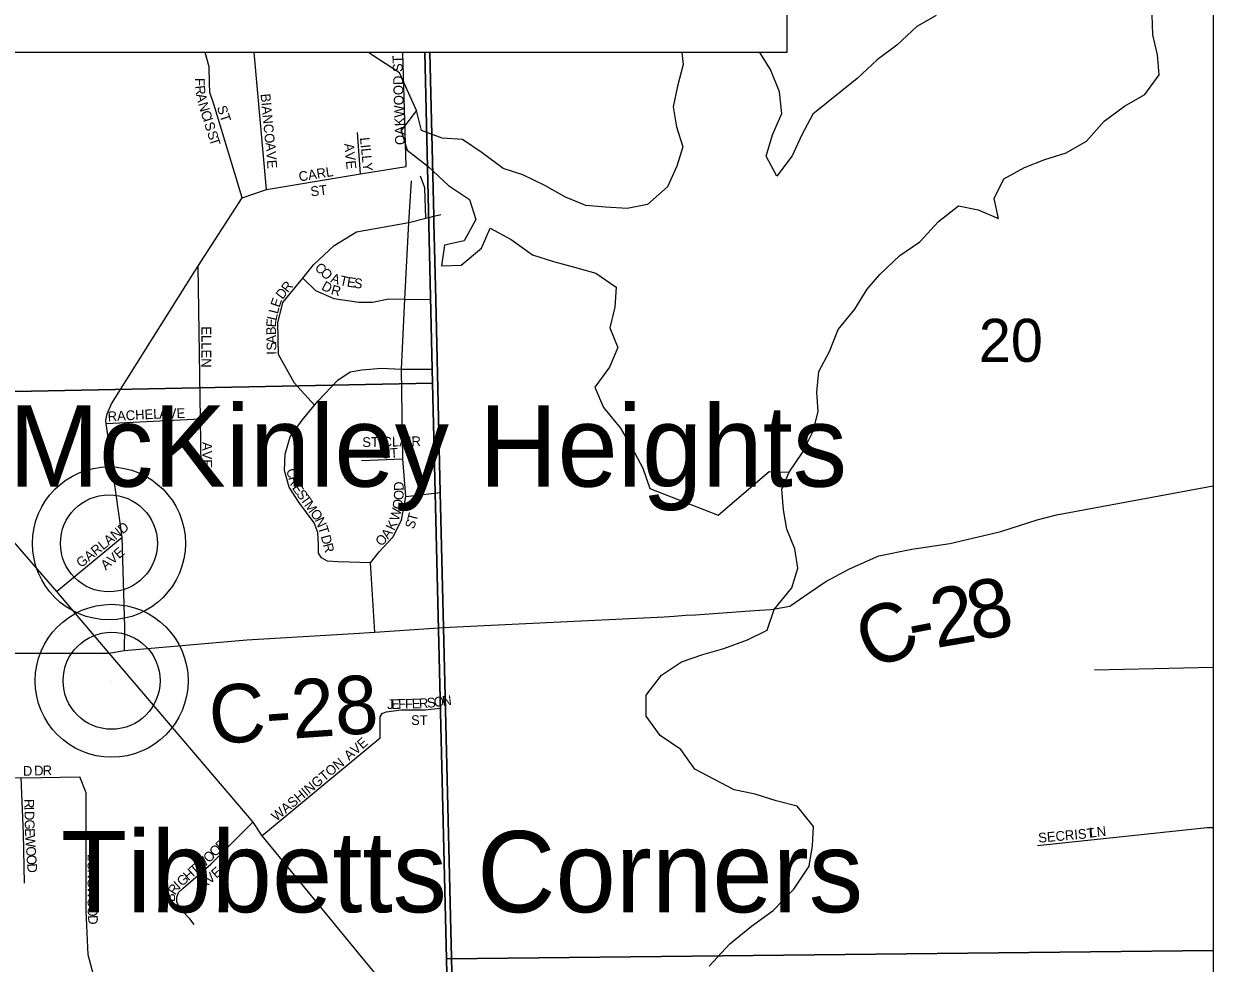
# Model space of a CAD drawing. Extents: x -37878.7 to -37844.7, y -19791.4 to -19769.4.
# Drawn here: x -37870.308 to -37869.15, y -19775.754 to -19774.84 of the extents above; entities that cross this region are included whole.
import ezdxf

# ---------------------------------------------------------------- set-up
doc = ezdxf.new("R2010")
doc.units = 0
for name, color, linetype in [('Default', 7, 'Continuous'), ('GM_X_City_Street', 7, 'Continuous'), ('GM_X_County_Road', 7, 'Continuous'), ('GM_X_County_Road_Text', 7, 'Continuous'), ('GM_X_Major_Lake', 7, 'Continuous'), ('GM_X_Minor_River', 7, 'Continuous'), ('GM_X_Section', 7, 'Continuous'), ('GM_X_Section_Text', 7, 'Continuous'), ('GM_X_State_Route', 7, 'Continuous'), ('GM_X_Township', 7, 'Continuous'), ('GM_X_Township_Subdivision', 7, 'Continuous'), ('GM_X_Township_Subdivision_Text', 7, 'Continuous'), ('GM_X_Unincorporated', 7, 'Continuous'), ('GM_X_Unincorporated_Text', 7, 'Continuous'), ('GM_X_US_Route', 7, 'Continuous'), ('SH_Data', 7, 'Continuous'), ('TX_P_1', 7, 'Continuous')]:
    doc.layers.add(name, color=color, linetype=linetype)

msp = doc.modelspace()

# ---------------------------------------------------------------- linework, layer by layer
at = {"layer": 'Default'}
for p, q in [((-37870.2249, -19775.3458), (-37870.2249, -19775.3458)), ((-37870.2223, -19775.4795), (-37870.2223, -19775.4795))]:
    msp.add_line(p, q, dxfattribs=at)
at = {"layer": 'GM_X_City_Street'}
for points in [[(-37869.5919, -19775.4109), (-37869.5804, -19775.4101), (-37869.5623, -19775.407), (-37869.5434, -19775.394), (-37869.5355, -19775.3885)], [(-37869.6542, -19775.4152), (-37869.6013, -19775.4115), (-37869.5919, -19775.4109)]]:
    msp.add_lwpolyline(points, dxfattribs=at)
at = {"layer": 'GM_X_County_Road'}
for points in [[(-37869.5355, -19775.3885), (-37869.5272, -19775.3829), (-37869.5043, -19775.3705), (-37869.4757, -19775.3579), (-37869.4436, -19775.3514), (-37869.4065, -19775.3459), (-37869.3805, -19775.3399), (-37869.3571, -19775.3344), (-37869.3216, -19775.3228), (-37869.3027, -19775.3181), (-37869.1504, -19775.2898)], [(-37869.6749, -19775.4166), (-37869.6638, -19775.4158), (-37869.6542, -19775.4152)], [(-37869.9866, -19775.4335), (-37869.9661, -19775.4323), (-37869.8993, -19775.4276), (-37869.8932, -19775.4273)], [(-37869.8932, -19775.4273), (-37869.6846, -19775.4173), (-37869.6749, -19775.4166)], [(-37870.2251, -19775.4526), (-37870.2099, -19775.45), (-37870.0908, -19775.4398), (-37869.9866, -19775.4335)]]:
    msp.add_lwpolyline(points, dxfattribs=at)
at = {"layer": 'GM_X_Major_Lake'}
msp.add_line((-37869.4852, -19775.0963), (-37869.4748, -19775.0842), dxfattribs=at)
for points in [[(-37869.4199, -19774.8323), (-37869.4389, -19774.8429), (-37869.4583, -19774.861), (-37869.4773, -19774.8753), (-37869.4967, -19774.8935), (-37869.5401, -19774.9282), (-37869.5508, -19774.9483), (-37869.56, -19774.9688), (-37869.5749, -19774.9884), (-37869.5854, -19774.969), (-37869.5792, -19774.9485), (-37869.57, -19774.9277), (-37869.5725, -19774.9064), (-37869.5811, -19774.8847), (-37869.5914, -19774.8684)], [(-37869.4748, -19775.0842), (-37869.4554, -19775.0657), (-37869.436, -19775.0525), (-37869.4177, -19775.0328), (-37869.3983, -19775.0173), (-37869.379, -19775.0212), (-37869.3594, -19775.0297), (-37869.3634, -19775.0103), (-37869.3542, -19774.9913), (-37869.3341, -19774.98), (-37869.3143, -19774.9725), (-37869.2935, -19774.9658), (-37869.2737, -19774.9545), (-37869.2566, -19774.9352), (-37869.2368, -19774.9205), (-37869.217, -19774.9092), (-37869.2029, -19774.8899), (-37869.2047, -19774.8705), (-37869.2091, -19774.8511), (-37869.2097, -19774.8317)], [(-37869.6675, -19774.8684), (-37869.6663, -19774.8798), (-37869.6717, -19774.901), (-37869.676, -19774.9211), (-37869.6727, -19774.9405), (-37869.6664, -19774.9599), (-37869.6722, -19774.9789), (-37869.6814, -19774.999), (-37869.7008, -19775.016), (-37869.7205, -19775.0201), (-37869.7417, -19775.0188), (-37869.761, -19775.0172), (-37869.7806, -19775.0091), (-37869.8006, -19774.9977), (-37869.8221, -19774.9873), (-37869.8414, -19774.9812), (-37869.8618, -19774.9659), (-37869.881, -19774.9529), (-37869.9007, -19774.9516), (-37869.9207, -19774.944), (-37869.9255, -19774.9246), (-37869.9404, -19774.9442), (-37869.9348, -19774.9633), (-37869.9145, -19774.9789), (-37869.8945, -19774.9976), (-37869.8742, -19775.0114), (-37869.8678, -19775.0308), (-37869.8793, -19775.0516), (-37869.8983, -19775.0557), (-37869.9014, -19775.0758), (-37869.8821, -19775.0751)], [(-37869.8821, -19775.0751), (-37869.8623, -19775.0585), (-37869.8539, -19775.0392), (-37869.8335, -19775.0503), (-37869.8128, -19775.0652), (-37869.7924, -19775.0717), (-37869.772, -19775.0772), (-37869.7512, -19775.0829), (-37869.7312, -19775.0967), (-37869.7328, -19775.1161), (-37869.7375, -19775.1362), (-37869.7296, -19775.1552), (-37869.7377, -19775.1745), (-37869.7522, -19775.1938), (-37869.7436, -19775.2136), (-37869.7271, -19775.2338), (-37869.7159, -19775.2532), (-37869.7054, -19775.2726), (-37869.6987, -19775.2924), (-37869.6322, -19775.3185), (-37869.5823, -19775.2758), (-37869.563, -19775.2767), (-37869.55, -19775.2574), (-37869.5397, -19775.2365), (-37869.5347, -19775.2176), (-37869.5361, -19775.1986), (-37869.534, -19775.1785), (-37869.5237, -19775.1592), (-37869.5152, -19775.1376), (-37869.4992, -19775.1179), (-37869.487, -19775.0986), (-37869.4852, -19775.0963)]]:
    msp.add_lwpolyline(points, dxfattribs=at)
at = {"layer": 'GM_X_Minor_River'}
for points in [[(-37869.9255, -19774.9246), (-37869.9421, -19774.8881), (-37869.9702, -19774.8697), (-37869.9719, -19774.8684)], [(-37869.6409, -19775.7571), (-37869.6207, -19775.7355), (-37869.5998, -19775.7182), (-37869.5785, -19775.7031), (-37869.5583, -19775.6823), (-37869.5434, -19775.6599), (-37869.5403, -19775.6402), (-37869.5394, -19775.6212), (-37869.5552, -19775.6014), (-37869.5756, -19775.5964), (-37869.596, -19775.5898), (-37869.6164, -19775.5856), (-37869.6549, -19775.5656), (-37869.6684, -19775.5462), (-37869.6884, -19775.5328), (-37869.7023, -19775.5138), (-37869.7022, -19775.4936), (-37869.6873, -19775.474), (-37869.6679, -19775.4611), (-37869.647, -19775.454), (-37869.6266, -19775.448), (-37869.6034, -19775.4398), (-37869.5844, -19775.4304), (-37869.5775, -19775.4103), (-37869.5603, -19775.3891), (-37869.5545, -19775.3701), (-37869.5574, -19775.3511), (-37869.5653, -19775.3321), (-37869.5686, -19775.3131), (-37869.57, -19775.293), (-37869.563, -19775.2767)]]:
    msp.add_lwpolyline(points, dxfattribs=at)
at = {"layer": 'GM_X_Section'}
for points in [[(-37869.9174, -19774.8684), (-37869.91, -19775.19), (-37871.0324, -19775.2124), (-37871.041, -19774.8684)], [(-37869.1504, -19775.742), (-37869.8966, -19775.75), (-37869.91, -19775.19), (-37869.9174, -19774.8684)], [(-37869.1504, -19776.7884), (-37869.8722, -19776.7987), (-37869.8839, -19776.3111), (-37869.8966, -19775.75), (-37869.1504, -19775.742)]]:
    msp.add_lwpolyline(points, dxfattribs=at)
msp.add_lwpolyline([(-37869.91, -19775.19), (-37869.8966, -19775.75), (-37869.8839, -19776.3111), (-37871.0074, -19776.3279), (-37871.0324, -19775.2124)], close=True, dxfattribs=at)
at = {"layer": 'GM_X_State_Route'}
msp.add_lwpolyline([(-37870.5559, -19775.4526), (-37870.5114, -19775.4526), (-37870.4536, -19775.4531), (-37870.4247, -19775.4526), (-37870.3932, -19775.4521), (-37870.3695, -19775.4526), (-37870.2251, -19775.4526)], dxfattribs=at)
at = {"layer": 'GM_X_Township'}
for points in [[(-37869.8525, -19777.3854), (-37869.8535, -19777.3423), (-37869.854, -19777.3235), (-37869.8592, -19777.1489), (-37869.8891, -19775.8564), (-37869.8993, -19775.4276), (-37869.9025, -19775.2964), (-37869.9069, -19775.1088), (-37869.9087, -19775.0336), (-37869.9089, -19775.0274), (-37869.9127, -19774.8684)], [(-37869.9127, -19774.8684), (-37869.9089, -19775.0274), (-37869.9087, -19775.0336), (-37869.9069, -19775.1088), (-37869.9025, -19775.2964), (-37869.8993, -19775.4276), (-37869.8891, -19775.8564), (-37869.8592, -19777.1489), (-37869.854, -19777.3235), (-37869.8535, -19777.3423), (-37869.8525, -19777.3854)]]:
    msp.add_lwpolyline(points, dxfattribs=at)
at = {"layer": 'GM_X_Township_Subdivision'}
for points in [[(-37870.0953, -19775.0095), (-37870.1023, -19774.9861), (-37870.1228, -19774.9186), (-37870.1268, -19774.9072), (-37870.1271, -19774.898), (-37870.1273, -19774.8821), (-37870.1313, -19774.8684)], [(-37870.0715, -19775.0014), (-37870.0836, -19774.8684)], [(-37869.9358, -19774.9792), (-37869.939, -19774.8684)], [(-37869.9802, -19774.9863), (-37869.9831, -19774.9461)], [(-37870.0953, -19775.0095), (-37870.0715, -19775.0014), (-37869.9802, -19774.9863), (-37869.9358, -19774.9792)], [(-37869.9661, -19775.4323), (-37869.9705, -19775.3648), (-37869.9621, -19775.354), (-37869.9487, -19775.3397), (-37869.9403, -19775.3232), (-37869.9361, -19775.3003), (-37869.9389, -19775.2637), (-37869.9403, -19775.1763), (-37869.9369, -19775.1082), (-37869.9331, -19775.0335), (-37869.9304, -19774.993)], [(-37869.9164, -19775.0293), (-37869.9176, -19775), (-37869.9217, -19774.9886)], [(-37870.2099, -19775.45), (-37870.2093, -19775.4274), (-37870.212, -19775.3397), (-37870.2277, -19775.2293), (-37870.2278, -19775.2263), (-37870.2267, -19775.2198), (-37870.2225, -19775.2102), (-37870.1414, -19775.081), (-37870.1385, -19775.0766), (-37870.0953, -19775.0095)], [(-37870.0249, -19775.2115), (-37870.0442, -19775.1898), (-37870.0598, -19775.1622), (-37870.0606, -19775.1314), (-37870.0558, -19775.1114), (-37870.0361, -19775.0877), (-37870.0258, -19775.0747), (-37870.0058, -19775.0559), (-37869.9839, -19775.0427), (-37869.9331, -19775.0335)], [(-37869.9331, -19775.0335), (-37869.9164, -19775.0293), (-37869.9124, -19775.0283)], [(-37869.9124, -19775.0283), (-37869.9089, -19775.0274), (-37869.9021, -19775.0257)], [(-37870.1385, -19775.0766), (-37870.1362, -19775.2247), (-37870.1355, -19775.2714)], [(-37870.0361, -19775.0877), (-37870.0238, -19775.0999), (-37870.0062, -19775.1075), (-37869.9819, -19775.111), (-37869.9683, -19775.111), (-37869.9527, -19775.1078), (-37869.9369, -19775.1082), (-37869.9119, -19775.1084)], [(-37869.9705, -19775.3648), (-37869.9911, -19775.3642), (-37870.0021, -19775.3638), (-37870.0121, -19775.3632), (-37870.0181, -19775.3598), (-37870.0209, -19775.3554), (-37870.0209, -19775.3472), (-37870.0215, -19775.3353), (-37870.0253, -19775.3259), (-37870.0403, -19775.3058), (-37870.0497, -19775.2911), (-37870.0541, -19775.2748), (-37870.0535, -19775.2591), (-37870.0485, -19775.2422), (-37870.0369, -19775.2259), (-37870.0249, -19775.2115), (-37870.0212, -19775.2071), (-37870.0021, -19775.187), (-37869.9902, -19775.1788), (-37869.9789, -19775.177), (-37869.9597, -19775.1754), (-37869.9403, -19775.1763), (-37869.911, -19775.1763)], [(-37870.2277, -19775.2293), (-37870.1362, -19775.2247)], [(-37869.979, -19775.2653), (-37869.9389, -19775.2637)], [(-37869.9361, -19775.3003), (-37869.9025, -19775.2964)], [(-37870.276, -19775.3927), (-37870.212, -19775.3397)], [(-37869.1504, -19775.4666), (-37869.2659, -19775.4693)], [(-37869.9551, -19775.5097), (-37869.9402, -19775.5077), (-37869.9171, -19775.5078), (-37869.9027, -19775.5061)], [(-37870.0761, -19775.6302), (-37869.961, -19775.535), (-37869.9609, -19775.5146), (-37869.9589, -19775.5112), (-37869.9551, -19775.5097)], [(-37870.3695, -19775.5729), (-37870.3102, -19775.5739), (-37870.2532, -19775.573)], [(-37870.307, -19775.6765), (-37870.3081, -19775.628), (-37870.3102, -19775.5739)], [(-37870.2258, -19775.806), (-37870.2388, -19775.7704), (-37870.2451, -19775.7462), (-37870.2472, -19775.7032), (-37870.2472, -19775.6527), (-37870.2472, -19775.5886), (-37870.2532, -19775.573)], [(-37870.142, -19775.7165), (-37870.1463, -19775.7111), (-37870.1534, -19775.7038), (-37870.1573, -19775.698), (-37870.1589, -19775.6946), (-37870.1588, -19775.6901), (-37870.1573, -19775.6856), (-37870.1528, -19775.6812), (-37870.1259, -19775.658), (-37870.085, -19775.6171)], [(-37869.3213, -19775.6396), (-37869.1561, -19775.6222), (-37869.1504, -19775.6221)]]:
    msp.add_lwpolyline(points, dxfattribs=at)
at = {"layer": 'GM_X_Unincorporated'}
for centre, radius in [((-37870.2249, -19775.3458), 0.0744), ((-37870.2249, -19775.3458), 0.0472), ((-37870.2223, -19775.4795), 0.0744), ((-37870.2223, -19775.4795), 0.0472)]:
    msp.add_circle(centre, radius, dxfattribs=at)
at = {"layer": 'GM_X_US_Route'}
for points in [[(-37870.4728, -19775.163), (-37870.455, -19775.1876), (-37870.3956, -19775.2549), (-37870.276, -19775.3927), (-37870.2251, -19775.4526)], [(-37870.2251, -19775.4526), (-37870.085, -19775.6171), (-37870.0761, -19775.6302), (-37870.0384, -19775.6761)], [(-37870.0384, -19775.6761), (-37869.9733, -19775.7555), (-37869.8891, -19775.8564), (-37869.8384, -19775.9237), (-37869.7923, -19775.98), (-37869.7601, -19776.0241), (-37869.745, -19776.0523), (-37869.7421, -19776.0678), (-37869.7288, -19776.105), (-37869.708, -19776.1606), (-37869.6824, -19776.2284), (-37869.6651, -19776.2779), (-37869.6516, -19776.3363), (-37869.6381, -19776.4743), (-37869.6331, -19776.5413), (-37869.6291, -19776.5618), (-37869.6234, -19776.5817), (-37869.5984, -19776.6319), (-37869.5916, -19776.6444)]]:
    msp.add_lwpolyline(points, dxfattribs=at)
at = {"layer": 'SH_Data'}
msp.add_line((-37869.1504, -19770.3854), (-37869.1504, -19777.3854), dxfattribs=at)
at = {"layer": 'TX_P_1'}
for p, q in [((-37869.5652, -19774.2693), (-37869.5652, -19774.8684)), ((-37869.5652, -19774.8684), (-37871.544, -19774.8684))]:
    msp.add_line(p, q, dxfattribs=at)

# ---------------------------------------------------------------- texts
at = {"layer": 'GM_X_County_Road_Text'}
for s, height, rotation, p in [('8', 0.0568, 12.2769, (-37869.383, -19775.4412)), ('2', 0.0568, 9.7335, (-37869.4202, -19775.4477)), ('C', 0.0568, 24.6883, (-37869.4817, -19775.4704)), ('-', 0.0568, 11.0038, (-37869.4427, -19775.4521)), ('C-28', 0.05682, 4.0142, (-37870.1257, -19775.5414))]:
    msp.add_text(s, height=height, rotation=rotation, dxfattribs=at).set_placement(p)
at = {"layer": 'GM_X_Section_Text'}
msp.add_text('20', height=0.04186, rotation=0, dxfattribs=at).set_placement((-37869.3784, -19775.1692))
at = {"layer": 'GM_X_Township_Subdivision_Text'}
for s, rotation, p in [('OAKWOOD ST', 91.8466, (-37869.9368, -19774.9581)), ('F', 270.3825, (-37870.1412, -19774.893)), ('R', 276.1676, (-37870.1411, -19774.9008)), ('A', 281.9071, (-37870.1401, -19774.9092)), ('N', 286.2625, (-37870.1382, -19774.9181)), ('BIANCO', 275.3905, (-37870.0774, -19774.9087)), ('C', 287.6379, (-37870.1358, -19774.9264)), ('ST', 288.4262, (-37870.12, -19774.9216)), ('I', 287.6524, (-37870.1335, -19774.9335)), ('S', 287.6271, (-37870.1323, -19774.9375)), ('S', 287.6531, (-37870.1295, -19774.9462)), ('T', 287.6276, (-37870.1275, -19774.9526)), ('LILLY', 275.7076, (-37869.9807, -19774.9512)), ('AVE', 274.0831, (-37870.0724, -19774.9562)), ('AVE', 275.9027, (-37869.9961, -19774.957)), ('CARL', 9.2121, (-37870.0395, -19774.9938)), ('ST', 7.1217, (-37870.0282, -19775.0083)), ('C', 317.5254, (-37870.0254, -19775.0787)), ('O', 317.5499, (-37870.0199, -19775.0837)), ('R', 50.7029, (-37870.0509, -19775.1025)), ('D', 332.213, (-37870.0189, -19775.0985)), ('A', 342.5759, (-37870.0098, -19775.0916)), ('T', 347.5061, (-37870.001, -19775.0943)), ('E', 351.7378, (-37869.9938, -19775.0959)), ('S', 351.5665, (-37869.9872, -19775.0969)), ('D', 52.2755, (-37870.056, -19775.1091)), ('R', 344.9218, (-37870.0095, -19775.1032)), ('E', 71.3663, (-37870.059, -19775.1168)), ('L', 77.6105, (-37870.062, -19775.1295)), ('L', 75.3906, (-37870.0606, -19775.1231)), ('ELLEN', 270, (-37870.1349, -19775.1347)), ('B', 91.4087, (-37870.0623, -19775.1431)), ('E', 85.8161, (-37870.0625, -19775.1358)), ('A', 91.4209, (-37870.0621, -19775.1514)), ('S', 91.4443, (-37870.0619, -19775.1581)), ('I', 91.3988, (-37870.0618, -19775.1622)), ('RACHEL', 3.0668, (-37870.2259, -19775.2271)), ('AVE', 1.9774, (-37870.1759, -19775.2246)), ('ST CLAIR', 0.9387, (-37869.9783, -19775.2521)), ('AVE', 270, (-37870.1341, -19775.2472)), ('CT', 3.1785, (-37869.9602, -19775.2633)), ('C', 284.4309, (-37870.0525, -19775.2743)), ('R', 286.6799, (-37870.0505, -19775.2819)), ('E', 303.3648, (-37870.0471, -19775.2918)), ('D', 93.0659, (-37869.9379, -19775.2945)), ('S', 305.748, (-37870.0431, -19775.2978)), ('T', 305.714, (-37870.0392, -19775.3032)), ('O', 86.739, (-37869.9384, -19775.3039)), ('M', 305.7254, (-37870.0354, -19775.3086)), ('W', 74.3872, (-37869.9431, -19775.3247)), ('O', 80.0124, (-37869.94, -19775.3133)), ('O', 305.7092, (-37870.0295, -19775.3167)), ('N', 294.5462, (-37870.0249, -19775.323)), ('K', 64.1782, (-37869.9474, -19775.334)), ('S', 67.8992, (-37869.9286, -19775.3327)), ('T', 75.3212, (-37869.9257, -19775.3252)), ('GARLAND', 39.0532, (-37870.252, -19775.37)), ('T', 287.2253, (-37870.0216, -19775.3303)), ('A', 53.6443, (-37869.9533, -19775.3423)), ('D', 285.1468, (-37870.0189, -19775.339)), ('R', 284.9111, (-37870.0168, -19775.347)), ('O', 47.6278, (-37869.9597, -19775.3493)), ('AVE', 40.8146, (-37870.228, -19775.3723)), ('E', 1.3386, (-37869.9501, -19775.507)), ('F', 1.351, (-37869.9434, -19775.5068)), ('F', 1.3522, (-37869.9367, -19775.5067)), ('E', 1.3386, (-37869.9301, -19775.5065)), ('R', 3.2827, (-37869.923, -19775.5063)), ('S', 6.6909, (-37869.9149, -19775.5059)), ('O', 7.126, (-37869.9082, -19775.5051)), ('N', 7.1196, (-37869.9, -19775.504)), ('J', 1.3556, (-37869.9542, -19775.5071)), ('ST', 0, (-37869.9309, -19775.5225)), ('AVE', 40.8174, (-37869.9912, -19775.5575)), ('WASHINGTON', 39.8044, (-37870.062, -19775.6167)), ('D', 1.2545, (-37870.3085, -19775.572)), ('D', 1.6834, (-37870.2976, -19775.5717)), ('R', 1.6761, (-37870.2893, -19775.5715)), ('R', 271.4573, (-37870.3074, -19775.5946)), ('I', 271.4425, (-37870.3072, -19775.6021)), ('D', 271.4428, (-37870.3071, -19775.6063)), ('G', 271.4633, (-37870.3069, -19775.6146)), ('E', 272.2588, (-37870.3067, -19775.6231)), ('SECRIST', 5.1935, (-37869.3202, -19775.6371)), ('LN', 6.0111, (-37869.2702, -19775.6321)), ('W', 273.5657, (-37870.3064, -19775.63)), ('D', 44.9992, (-37870.1157, -19775.6454)), ('O', 273.7325, (-37870.3057, -19775.6409)), ('O', 44.0674, (-37870.1277, -19775.6572)), ('O', 44.9913, (-37870.1216, -19775.6513)), ('O', 273.7181, (-37870.3052, -19775.6492)), ('D', 273.7325, (-37870.3046, -19775.6575)), ('O', 270, (-37870.2457, -19775.6547)), ('L', 270.0273, (-37870.2457, -19775.648)), ('T', 40.988, (-37870.1413, -19775.6691)), ('W', 41.2828, (-37870.1362, -19775.6647)), ('N', 270.0154, (-37870.2457, -19775.663)), ('G', 41.2497, (-37870.1538, -19775.68)), ('H', 41.0091, (-37870.1476, -19775.6745)), ('V', 40.5323, (-37870.1268, -19775.6778)), ('E', 41.6728, (-37870.1203, -19775.6723)), ('G', 270, (-37870.2457, -19775.6714)), ('W', 270.0138, (-37870.2457, -19775.6797)), ('R', 56.687, (-37870.1606, -19775.6886)), ('I', 42.7897, (-37870.1568, -19775.6828)), ('A', 40.3737, (-37870.1331, -19775.6832)), ('O', 270.0219, (-37870.2457, -19775.6905)), ('B', 83.8435, (-37870.161, -19775.695)), ('O', 271.9089, (-37870.2457, -19775.6992)), ('D', 273.5236, (-37870.2454, -19775.7078))]:
    msp.add_text(s, height=0.00947, rotation=rotation, dxfattribs=at).set_placement(p)
at = {"layer": 'GM_X_Unincorporated_Text'}
for s, p in [('McKinley Heights', (-37870.3225, -19775.2906)), ('Tibbetts Corners', (-37870.2717, -19775.7047))]:
    msp.add_text(s, height=0.078977, rotation=0, dxfattribs=at).set_placement(p)

doc.saveas('drawing.dxf')
